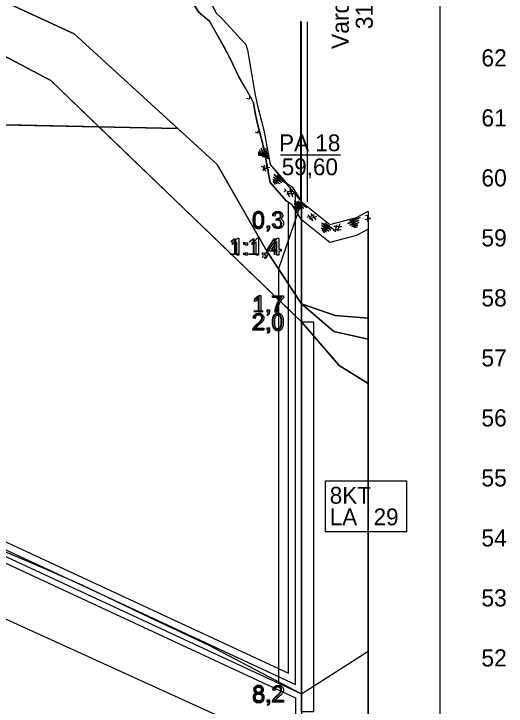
# Model space of a CAD drawing. Extents: x 532503 to 539665, y 6557663 to 6561526.
# Drawn here: x 537779.4 to 537943.4, y 6559649.9 to 6559880.7 of the extents above; entities that cross this region are included whole.
import ezdxf

# ---------------------------------------------------------------- set-up
doc = ezdxf.new("R2010")
doc.units = 0
for name, color, linetype in [('Default', 7, 'Continuous'), ('GEOLPUNKT', 7, 'Continuous'), ('illumineerimisjooned', 7, 'Continuous'), ('kataster', 7, 'Continuous'), ('maapind varasem', 7, 'Continuous'), ('mõõtpost parem', 7, 'Continuous'), ('PIIR', 7, 'Continuous'), ('Plokid', 7, 'Continuous'), ('Proovid', 7, 'Continuous'), ('RELJEEF', 7, 'Continuous'), ('Täide', 7, 'Continuous'), ('Veetase', 7, 'Continuous')]:
    doc.layers.add(name, color=color, linetype=linetype)

msp = doc.modelspace()

# ---------------------------------------------------------------- linework, layer by layer
at = {"layer": 'Default'}
for points in [[(537303.91, 6559920.78), (537332.99, 6559924), (537470.8, 6559937.4), (537470.8, 6559937.4), (537596.15, 6559901.6), (537596.15, 6559901.6), (537633.32, 6559922.6), (537745.67, 6559898.93), (537799.52, 6559873.96), (537847.17, 6559830.4), (537863.68, 6559801.53), (537875.25, 6559784), (537886.02, 6559774.84), (537897.46, 6559772.19)], [(537332.99, 6559924), (537470.8, 6559937.4), (537470.8, 6559937.4), (537596.15, 6559901.6), (537596.15, 6559901.6), (537633.32, 6559922.6), (537727.66, 6559892.38), (537791.69, 6559858.5), (537875.25, 6559778)], [(537303.91, 6559847.71), (537332.99, 6559848), (537470.8, 6559849.4), (537596.15, 6559847.6), (537833.98, 6559842.46)], [(537864.75, 6559830.4), (537870.28, 6559824.24), (537871.44, 6559823.5), (537872.15, 6559823), (537875.25, 6559818), (537884.66, 6559810.4), (537893.55, 6559812.84), (537897.46, 6559814.89)], [(537875.25, 6559778), (537887.82, 6559763.5), (537887.82, 6559763.5), (537897.46, 6559757.41)], [(537470.8, 6559750.72), (537596.15, 6559761.6), (537596.15, 6559761.6), (537637.63, 6559750.4), (537658, 6559744.14), (537701.62, 6559730.4), (537705.43, 6559729.02), (537718.89, 6559723.97), (537747.42, 6559713.34), (537755.24, 6559710.4), (537786.09, 6559697.32), (537802.07, 6559690.4), (537824.66, 6559679.52), (537844.13, 6559670.4), (537875.25, 6559654), (537897.46, 6559668.25)]]:
    msp.add_lwpolyline(points, dxfattribs=at)
at = {"layer": 'GEOLPUNKT'}
for p, q in [((537868.25, 6559833.68), (537888.25, 6559833.68)), ((537875.25, 6559818), (537875.25, 6559518))]:
    msp.add_line(p, q, dxfattribs=at)
at = {"layer": 'illumineerimisjooned'}
for p, q in [((537877.25, 6559818), (537877.25, 6559878)), ((537873.25, 6559657.14), (537873.25, 6559821.22))]:
    msp.add_line(p, q, dxfattribs=at)
msp.add_lwpolyline([(537335, 6559734.24), (537596.35, 6559763.64), (537748.15, 6559715.21), (537873.25, 6559657.14)], dxfattribs=at)
at = {"layer": 'kataster'}
msp.add_line((537875.04, 6559818.25), (537875.04, 6559878.25), dxfattribs=at)
at = {"layer": 'maapind varasem'}
msp.add_lwpolyline([(537776.56, 6559922.34), (537828.68, 6559905.51), (537836.34, 6559895.12), (537841.86, 6559890.4), (537846.88, 6559880.76), (537848.07, 6559879.75), (537848.76, 6559879.05), (537856.66, 6559870.4), (537857.06, 6559869.29), (537857.12, 6559869.07), (537857.16, 6559868.91), (537857.2, 6559868.69), (537857.69, 6559866), (537859.64, 6559854.28), (537860.46, 6559850.4), (537862.71, 6559841.91), (537864.75, 6559830.4), (537875.25, 6559818), (537884.66, 6559810.4), (537893.55, 6559812.84), (537897.46, 6559814.89)], dxfattribs=at)
at = {"layer": 'mõõtpost parem'}
msp.add_line((537921.46, 6559506), (537921.46, 6559986), dxfattribs=at)
at = {"layer": 'PIIR'}
for p, q in [((537875.25, 6559818), (537875.25, 6559878)), ((537875.25, 6559654), (537875.25, 6559818))]:
    msp.add_line(p, q, dxfattribs=at)
msp.add_lwpolyline([(537333, 6559732.01), (537596.15, 6559761.6), (537747.42, 6559713.34), (537875.25, 6559654)], dxfattribs=at)
at = {"layer": 'Plokid'}
for p, q in [((537870.85, 6559660.9), (537870.85, 6559817.88)), ((537873.25, 6559652.73), (537873.25, 6559518.45))]:
    msp.add_line(p, q, dxfattribs=at)
for points in [[(537337.4, 6559924.36), (537471.34, 6559937.39), (537471.34, 6559937.39), (537596.69, 6559901.59), (537596.69, 6559901.59), (537633.32, 6559922.6), (537727.66, 6559892.38), (537791.65, 6559858.53), (537791.67, 6559858.53), (537791.69, 6559858.5), (537870.85, 6559782.24)], [(537832.45, 6559889.51), (537838.46, 6559885.32), (537840.92, 6559881.3), (537844.55, 6559878.21), (537851.47, 6559865.77), (537854.28, 6559859.93), (537858.59, 6559852.33), (537859.19, 6559851), (537859.64, 6559848.28)], [(537859.64, 6559848.28), (537860.46, 6559844.4), (537862.71, 6559835.91), (537864.75, 6559824.4), (537870.28, 6559818.24), (537870.85, 6559817.88)], [(537337.4, 6559736.93), (537596.59, 6559766.08), (537749.02, 6559717.45), (537870.85, 6559660.9)], [(537337.4, 6559730.49), (537595.95, 6559759.57), (537746.69, 6559711.48), (537873.25, 6559652.73)]]:
    msp.add_lwpolyline(points, dxfattribs=at)
at = {"layer": 'Proovid'}
for points in [[(537866.34, 6559813.25), (537865.65, 6559813.38)], [(537866.94, 6559811.86), (537867.01, 6559812.46)], [(537865.58, 6559810.69), (537866.27, 6559810.78)], [(537863.92, 6559808.1), (537863.73, 6559808.39)], [(537863.78, 6559809.2), (537863.78, 6559809.99), (537864.56, 6559809.99), (537864.56, 6559809.2)], [(537864.16, 6559809.2), (537863.78, 6559809.2)], [(537859.58, 6559784.76), (537859.58, 6559785.42)], [(537861.64, 6559781.2), (537860.95, 6559781.2), (537860.95, 6559785.59)], [(537861.2, 6559786.83), (537861.64, 6559786.83), (537861.64, 6559781.2)], [(537865.62, 6559786.07), (537865.62, 6559786.73), (537869.25, 6559786.73), (537869.25, 6559786.2)], [(537868.36, 6559786.07), (537865.62, 6559786.07)], [(537863.92, 6559780.1), (537863.73, 6559780.39)], [(537863.78, 6559781.2), (537863.78, 6559781.99), (537864.56, 6559781.99), (537864.56, 6559781.2)], [(537864.16, 6559781.2), (537863.78, 6559781.2)], [(537867.11, 6559781.2), (537866.4, 6559781.2)], [(537859.82, 6559779.14), (537859.11, 6559779.21)], [(537862.69, 6559775.87), (537862.69, 6559775.2), (537858.99, 6559775.2)], [(537859.94, 6559775.87), (537862.69, 6559775.87)], [(537863.8, 6559775.2), (537863.8, 6559775.99), (537864.58, 6559775.99), (537864.58, 6559775.2)], [(537863.94, 6559774.1), (537863.75, 6559774.39)], [(537864.19, 6559775.2), (537863.8, 6559775.2)], [(537866.38, 6559655.14), (537865.67, 6559655.21)], [(537863.83, 6559651.2), (537863.83, 6559651.99), (537864.62, 6559651.99), (537864.62, 6559651.2)], [(537864.22, 6559651.2), (537863.83, 6559651.2)], [(537869.25, 6559651.87), (537869.25, 6559651.2), (537865.55, 6559651.2)], [(537866.5, 6559651.87), (537869.25, 6559651.87)], [(537863.98, 6559650.1), (537863.79, 6559650.39)]]:
    msp.add_lwpolyline(points, dxfattribs=at)
for points in [[(537875.25, 6559778), (537879.25, 6559778), (537879.25, 6559648), (537875.25, 6559648)], [(537883.25, 6559725), (537910.25, 6559725), (537910.25, 6559708), (537883.25, 6559708)]]:
    msp.add_lwpolyline(points, close=True, dxfattribs=at)
for points in [[(537859.05, 6559811.97), (537859.05, 6559812.96), (537859.26, 6559813.57), (537859.46, 6559814.17), (537859.87, 6559814.5), (537860.27, 6559814.83), (537860.88, 6559814.83), (537861.33, 6559814.83), (537861.67, 6559814.64), (537862.01, 6559814.46), (537862.23, 6559814.12), (537862.45, 6559813.78), (537862.58, 6559813.29), (537862.7, 6559812.8), (537862.7, 6559811.97), (537862.7, 6559810.98), (537862.5, 6559810.38), (537862.3, 6559809.77), (537861.9, 6559809.44), (537861.49, 6559809.11), (537860.88, 6559809.11), (537860.07, 6559809.11), (537859.61, 6559809.69), (537859.05, 6559810.39), (537859.05, 6559811.97)], [(537865.65, 6559813.38), (537865.78, 6559814.07), (537866.22, 6559814.45), (537866.67, 6559814.83), (537867.33, 6559814.83), (537867.79, 6559814.83), (537868.18, 6559814.63), (537868.56, 6559814.43), (537868.77, 6559814.09), (537868.97, 6559813.75), (537868.97, 6559813.37), (537868.97, 6559813.01), (537868.78, 6559812.71), (537868.58, 6559812.42), (537868.2, 6559812.24), (537868.7, 6559812.13), (537868.97, 6559811.77), (537869.25, 6559811.4), (537869.25, 6559810.86), (537869.25, 6559810.13), (537868.71, 6559809.62), (537868.18, 6559809.11), (537867.36, 6559809.11), (537866.62, 6559809.11), (537866.14, 6559809.55), (537865.65, 6559809.99), (537865.58, 6559810.69)], [(537859.76, 6559811.97), (537859.76, 6559810.59), (537860.08, 6559810.13), (537860.41, 6559809.67), (537860.88, 6559809.67), (537861.35, 6559809.67), (537861.67, 6559810.13), (537862, 6559810.59), (537862, 6559811.97), (537862, 6559813.35), (537861.67, 6559813.8), (537861.35, 6559814.26), (537860.87, 6559814.26), (537860.4, 6559814.26), (537860.12, 6559813.86), (537859.76, 6559813.35), (537859.76, 6559811.97)], [(537867.01, 6559812.46), (537867.08, 6559812.45), (537867.12, 6559812.45), (537867.56, 6559812.45), (537867.91, 6559812.68), (537868.27, 6559812.91), (537868.27, 6559813.39), (537868.27, 6559813.77), (537868.01, 6559814.01), (537867.75, 6559814.26), (537867.35, 6559814.26), (537866.95, 6559814.26), (537866.68, 6559814.01), (537866.41, 6559813.76), (537866.34, 6559813.25)], [(537866.27, 6559810.78), (537866.39, 6559810.19), (537866.67, 6559809.94), (537866.95, 6559809.68), (537867.36, 6559809.68), (537867.85, 6559809.68), (537868.18, 6559810.01), (537868.52, 6559810.35), (537868.52, 6559810.85), (537868.52, 6559811.32), (537868.21, 6559811.63), (537867.9, 6559811.94), (537867.42, 6559811.94), (537867.23, 6559811.94), (537866.94, 6559811.86)], [(537863.73, 6559808.39), (537863.95, 6559808.49), (537864.05, 6559808.67), (537864.15, 6559808.86), (537864.16, 6559809.2)], [(537864.56, 6559809.2), (537864.56, 6559808.77), (537864.4, 6559808.51), (537864.25, 6559808.24), (537863.92, 6559808.1)], [(537859.58, 6559785.42), (537860.16, 6559785.69), (537860.59, 6559786.08), (537861.02, 6559786.46), (537861.2, 6559786.83)], [(537860.95, 6559785.59), (537860.71, 6559785.35), (537860.3, 6559785.11), (537859.9, 6559784.87), (537859.58, 6559784.76)], [(537866.4, 6559781.2), (537866.42, 6559781.87), (537866.66, 6559782.8), (537866.91, 6559783.74), (537867.38, 6559784.61), (537867.84, 6559785.48), (537868.36, 6559786.07)], [(537869.25, 6559786.2), (537868.71, 6559785.63), (537868.19, 6559784.68), (537867.66, 6559783.74), (537867.38, 6559782.74), (537867.17, 6559782.04), (537867.11, 6559781.2)], [(537858.99, 6559775.2), (537858.98, 6559775.45), (537859.07, 6559775.68), (537859.21, 6559776.06), (537859.52, 6559776.43), (537859.83, 6559776.79), (537860.42, 6559777.27), (537861.33, 6559778.02), (537861.65, 6559778.46), (537861.97, 6559778.9), (537861.97, 6559779.29), (537861.97, 6559779.7), (537861.68, 6559779.98), (537861.39, 6559780.26), (537860.92, 6559780.26), (537860.42, 6559780.26), (537860.12, 6559779.96), (537859.83, 6559779.66), (537859.82, 6559779.14)], [(537859.11, 6559779.21), (537859.19, 6559780), (537859.66, 6559780.41), (537860.13, 6559780.83), (537860.93, 6559780.83), (537861.74, 6559780.83), (537862.21, 6559780.38), (537862.68, 6559779.93), (537862.68, 6559779.27), (537862.68, 6559778.94), (537862.54, 6559778.61), (537862.4, 6559778.29), (537862.08, 6559777.93), (537861.77, 6559777.57), (537861.03, 6559776.94), (537860.41, 6559776.42), (537860.23, 6559776.24), (537860.06, 6559776.05), (537859.94, 6559775.87)], [(537863.73, 6559780.39), (537863.95, 6559780.49), (537864.05, 6559780.67), (537864.15, 6559780.86), (537864.16, 6559781.2)], [(537864.56, 6559781.2), (537864.56, 6559780.77), (537864.4, 6559780.51), (537864.25, 6559780.24), (537863.92, 6559780.1)], [(537865.6, 6559777.97), (537865.6, 6559778.96), (537865.8, 6559779.57), (537866.01, 6559780.17), (537866.41, 6559780.5), (537866.81, 6559780.83), (537867.42, 6559780.83), (537867.87, 6559780.83), (537868.21, 6559780.64), (537868.55, 6559780.46), (537868.77, 6559780.12), (537869, 6559779.78), (537869.12, 6559779.29), (537869.25, 6559778.8), (537869.25, 6559777.97), (537869.25, 6559776.98), (537869.04, 6559776.38), (537868.84, 6559775.77), (537868.44, 6559775.44), (537868.04, 6559775.11), (537867.42, 6559775.11), (537866.61, 6559775.11), (537866.15, 6559775.69), (537865.6, 6559776.39), (537865.6, 6559777.97)], [(537866.31, 6559777.97), (537866.31, 6559776.59), (537866.63, 6559776.13), (537866.95, 6559775.67), (537867.42, 6559775.67), (537867.89, 6559775.67), (537868.22, 6559776.13), (537868.54, 6559776.59), (537868.54, 6559777.97), (537868.54, 6559779.35), (537868.22, 6559779.8), (537867.9, 6559780.26), (537867.41, 6559780.26), (537866.94, 6559780.26), (537866.66, 6559779.86), (537866.31, 6559779.35), (537866.31, 6559777.97)], [(537863.75, 6559774.39), (537863.97, 6559774.49), (537864.07, 6559774.67), (537864.17, 6559774.86), (537864.19, 6559775.2)], [(537864.58, 6559775.2), (537864.58, 6559774.77), (537864.43, 6559774.51), (537864.27, 6559774.24), (537863.94, 6559774.1)], [(537860.18, 6559654.24), (537859.75, 6559654.4), (537859.54, 6559654.69), (537859.33, 6559654.98), (537859.33, 6559655.38), (537859.33, 6559655.99), (537859.77, 6559656.41), (537860.21, 6559656.83), (537860.94, 6559656.83), (537861.67, 6559656.83), (537862.12, 6559656.4), (537862.56, 6559655.98), (537862.56, 6559655.37), (537862.56, 6559654.98), (537862.36, 6559654.69), (537862.15, 6559654.4), (537861.74, 6559654.24), (537862.25, 6559654.08), (537862.52, 6559653.7), (537862.79, 6559653.33), (537862.79, 6559652.81), (537862.79, 6559652.09), (537862.29, 6559651.6), (537861.78, 6559651.11), (537860.95, 6559651.11), (537860.12, 6559651.11), (537859.61, 6559651.6), (537859.11, 6559652.09), (537859.11, 6559652.83), (537859.11, 6559653.37), (537859.38, 6559653.74), (537859.66, 6559654.11), (537860.18, 6559654.24)], [(537860.04, 6559655.41), (537860.04, 6559655.01), (537860.29, 6559654.76), (537860.55, 6559654.51), (537860.95, 6559654.51), (537861.35, 6559654.51), (537861.6, 6559654.76), (537861.85, 6559655.01), (537861.85, 6559655.37), (537861.85, 6559655.75), (537861.6, 6559656.01), (537861.34, 6559656.26), (537860.95, 6559656.26), (537860.55, 6559656.26), (537860.3, 6559656.01), (537860.04, 6559655.76), (537860.04, 6559655.41)], [(537865.55, 6559651.2), (537865.54, 6559651.45), (537865.63, 6559651.68), (537865.77, 6559652.06), (537866.08, 6559652.43), (537866.39, 6559652.79), (537866.98, 6559653.27), (537867.89, 6559654.02), (537868.21, 6559654.46), (537868.53, 6559654.9), (537868.53, 6559655.29), (537868.53, 6559655.7), (537868.24, 6559655.98), (537867.95, 6559656.26), (537867.48, 6559656.26), (537866.98, 6559656.26), (537866.68, 6559655.96), (537866.39, 6559655.66), (537866.38, 6559655.14)], [(537865.67, 6559655.21), (537865.75, 6559656), (537866.22, 6559656.41), (537866.69, 6559656.83), (537867.49, 6559656.83), (537868.3, 6559656.83), (537868.77, 6559656.38), (537869.24, 6559655.93), (537869.24, 6559655.27), (537869.24, 6559654.94), (537869.1, 6559654.61), (537868.96, 6559654.29), (537868.65, 6559653.93), (537868.33, 6559653.57), (537867.59, 6559652.94), (537866.97, 6559652.42), (537866.79, 6559652.24), (537866.62, 6559652.05), (537866.5, 6559651.87)], [(537859.81, 6559652.82), (537859.81, 6559652.53), (537859.95, 6559652.25), (537860.09, 6559651.98), (537860.36, 6559651.83), (537860.64, 6559651.67), (537860.96, 6559651.67), (537861.45, 6559651.67), (537861.77, 6559651.99), (537862.08, 6559652.31), (537862.08, 6559652.8), (537862.08, 6559653.3), (537861.76, 6559653.62), (537861.43, 6559653.95), (537860.93, 6559653.95), (537860.45, 6559653.95), (537860.13, 6559653.62), (537859.81, 6559653.3), (537859.81, 6559652.82)], [(537863.79, 6559650.39), (537864.01, 6559650.49), (537864.11, 6559650.67), (537864.21, 6559650.86), (537864.22, 6559651.2)], [(537864.62, 6559651.2), (537864.62, 6559650.77), (537864.46, 6559650.51), (537864.31, 6559650.24), (537863.98, 6559650.1)]]:
    msp.add_open_spline(points, degree=3, dxfattribs=at)
at = {"layer": 'RELJEEF'}
for p, q in [((537875.25, 6559818), (537867.54, 6559795.68)), ((537867.54, 6559795.68), (537867.54, 6559657.58))]:
    msp.add_line(p, q, dxfattribs=at)
for points in [[(537853.9, 6559805.9), (537854.34, 6559805.9), (537854.34, 6559800.28)], [(537860.42, 6559805.9), (537860.87, 6559805.9), (537860.87, 6559800.28)], [(537867, 6559800.28), (537867, 6559801.62), (537864.58, 6559801.62), (537864.58, 6559802.25), (537867.13, 6559805.88), (537867.69, 6559805.88), (537867.69, 6559802.25), (537868.45, 6559802.25), (537868.45, 6559801.62), (537867.69, 6559801.62), (537867.69, 6559800.28), (537867, 6559800.28)], [(537852.28, 6559803.83), (537852.28, 6559804.5)], [(537854.34, 6559800.28), (537853.66, 6559800.28), (537853.66, 6559804.66)], [(537856.49, 6559803.56), (537856.49, 6559804.34), (537857.27, 6559804.34), (537857.27, 6559803.56), (537856.49, 6559803.56)], [(537858.8, 6559803.83), (537858.8, 6559804.5)], [(537860.87, 6559800.28), (537860.18, 6559800.28), (537860.18, 6559804.66)], [(537867, 6559802.25), (537867, 6559804.78), (537865.25, 6559802.25), (537867, 6559802.25)], [(537856.49, 6559800.28), (537856.49, 6559801.06), (537857.27, 6559801.06), (537857.27, 6559800.28), (537856.49, 6559800.28)], [(537863, 6559800.28), (537863, 6559801.06), (537863.78, 6559801.06), (537863.78, 6559800.28)], [(537863.15, 6559799.17), (537862.95, 6559799.47)], [(537863.39, 6559800.28), (537863, 6559800.28)]]:
    msp.add_lwpolyline(points, dxfattribs=at)
for points in [[(537852.28, 6559804.5), (537852.86, 6559804.77), (537853.29, 6559805.15), (537853.72, 6559805.54), (537853.9, 6559805.9)], [(537858.8, 6559804.5), (537859.38, 6559804.77), (537859.81, 6559805.15), (537860.24, 6559805.54), (537860.42, 6559805.9)], [(537853.66, 6559804.66), (537853.41, 6559804.42), (537853.01, 6559804.19), (537852.6, 6559803.95), (537852.28, 6559803.83)], [(537860.18, 6559804.66), (537859.93, 6559804.42), (537859.53, 6559804.19), (537859.13, 6559803.95), (537858.8, 6559803.83)], [(537862.95, 6559799.47), (537863.17, 6559799.56), (537863.27, 6559799.75), (537863.38, 6559799.93), (537863.39, 6559800.28)], [(537863.78, 6559800.28), (537863.78, 6559799.85), (537863.63, 6559799.58), (537863.48, 6559799.32), (537863.15, 6559799.17)]]:
    msp.add_open_spline(points, degree=3, dxfattribs=at)
at = {"layer": 'Täide'}
for p, q in [((537745.67, 6559898.93), (537799.52, 6559873.96)), ((537833.98, 6559842.46), (537799.52, 6559873.96)), ((537799.52, 6559873.96), (537833.98, 6559842.46)), ((537791.69, 6559858.5), (537807.75, 6559843.03)), ((537859.19, 6559851), (537858.59, 6559852.33)), ((537807.75, 6559843.03), (537833.47, 6559818.25)), ((537833.98, 6559842.46), (537807.75, 6559843.03)), ((537833.98, 6559842.46), (537807.75, 6559843.03)), ((537807.75, 6559843.03), (537833.47, 6559818.25)), ((537807.75, 6559843.03), (537833.98, 6559842.46)), ((537847.17, 6559830.4), (537833.98, 6559842.46)), ((537847.17, 6559830.4), (537833.98, 6559842.46)), ((537833.98, 6559842.46), (537847.17, 6559830.4)), ((537847.17, 6559830.4), (537863.68, 6559801.53)), ((537833.47, 6559818.25), (537833.47, 6559818.25)), ((537833.47, 6559818.25), (537833.47, 6559818.25)), ((537833.47, 6559818.25), (537875.25, 6559778)), ((537897.46, 6559779.26), (537897.46, 6559808.89)), ((537863.68, 6559801.53), (537875.25, 6559784)), ((537886.02, 6559774.84), (537875.25, 6559784)), ((537886.45, 6559780.15), (537875.25, 6559784)), ((537875.25, 6559784), (537886.45, 6559780.15)), ((537897.46, 6559779.26), (537886.45, 6559780.15)), ((537886.45, 6559780.15), (537897.46, 6559779.26)), ((537875.25, 6559778), (537887.82, 6559763.5)), ((537897.46, 6559757.41), (537897.46, 6559779.26)), ((537897.46, 6559772.19), (537886.02, 6559774.84)), ((537897.46, 6559757.41), (537897.46, 6559772.19)), ((537887.82, 6559763.5), (537897.46, 6559757.41))]:
    msp.add_line(p, q, dxfattribs=at)
for points in [[(537897.46, 6559757.41), (537887.82, 6559763.5), (537875.25, 6559778), (537791.69, 6559858.5), (537727.66, 6559892.38), (537633.32, 6559922.6), (537596.15, 6559901.6), (537470.8, 6559937.4), (537332.99, 6559924), (537303.91, 6559920.78)], [(537799.52, 6559873.96), (537745.67, 6559898.93), (537633.32, 6559922.6)], [(537633.32, 6559922.6), (537727.66, 6559892.38), (537791.69, 6559858.5)], [(537775.61, 6559843.72), (537833.98, 6559842.46), (537799.52, 6559873.96), (537745.67, 6559898.93)], [(537858.59, 6559852.33), (537856.61, 6559855.9), (537854.28, 6559859.93), (537851.47, 6559865.77), (537849.43, 6559869.71), (537844.55, 6559878.21), (537841.95, 6559880.3), (537841.36, 6559880.95), (537840.92, 6559881.3), (537838.46, 6559885.32), (537832.45, 6559889.51)], [(537857.86, 6559853), (537857.85, 6559852.21), (537857.06, 6559852.48)], [(537807.75, 6559843.03), (537596.15, 6559847.6), (537470.8, 6559849.4)], [(537897.46, 6559808.89), (537893.55, 6559806.84), (537884.66, 6559804.4), (537875.25, 6559812), (537872.15, 6559817), (537871.44, 6559817.5), (537870.28, 6559818.24), (537864.75, 6559824.4), (537862.71, 6559835.91), (537860.46, 6559844.4), (537859.64, 6559848.28), (537859.19, 6559851)], [(537897.46, 6559757.41), (537887.82, 6559763.5), (537875.25, 6559778), (537833.47, 6559818.25), (537807.75, 6559843.03)], [(537860.72, 6559841.69), (537860.68, 6559840.9), (537859.9, 6559841.2)], [(537863.23, 6559835.91), (537864.07, 6559832.29), (537862.4, 6559836.55), (537863.16, 6559832.8), (537861.84, 6559835.92), (537862.43, 6559832.85), (537861.25, 6559835.34), (537861.68, 6559833.32), (537860.92, 6559834.68), (537860.95, 6559833.49)], [(537875.25, 6559784), (537863.68, 6559801.53), (537847.17, 6559830.4)], [(537875.25, 6559784), (537863.68, 6559801.53), (537847.17, 6559830.4)], [(537862.74, 6559830.23), (537862.7, 6559829.45), (537861.92, 6559829.74)], [(537862.22, 6559828.62), (537862.52, 6559828.67), (537862.66, 6559828.62), (537862.7, 6559829.45), (537863.77, 6559829.02), (537863.84, 6559829.86)], [(537864.68, 6559829.47), (537863.81, 6559829.32), (537862.7, 6559829.15), (537863.21, 6559828.24)], [(537863.97, 6559830.18), (537863.43, 6559830.08), (537863.81, 6559829.32), (537864.27, 6559828.44)], [(537867.1, 6559826.99), (537869.73, 6559824.35), (537866.05, 6559827.09), (537868.68, 6559824.31), (537865.91, 6559826.26), (537868.03, 6559823.97), (537865.72, 6559825.45), (537867.14, 6559823.97), (537865.78, 6559824.72), (537866.44, 6559823.73)], [(537869.59, 6559822.3), (537870.15, 6559821.74), (537869.4, 6559821.36)], [(537870.39, 6559820.53), (537870.64, 6559820.69), (537870.8, 6559820.69), (537870.53, 6559821.48), (537871.68, 6559821.48), (537871.43, 6559822.28)], [(537872.8, 6559820.66), (537871.92, 6559820.67), (537870.8, 6559820.69), (537871.14, 6559819.71)], [(537872.22, 6559821.49), (537871.68, 6559821.48), (537871.92, 6559820.67), (537872.22, 6559819.72)], [(537833.47, 6559818.25), (537833.47, 6559818.25), (537833.47, 6559818.25)], [(537833.47, 6559818.25), (537875.25, 6559778), (537887.82, 6559763.5), (537897.46, 6559757.41)], [(537874, 6559818.32), (537877.02, 6559816.14), (537872.95, 6559818.26), (537875.99, 6559815.93), (537872.94, 6559817.42), (537875.41, 6559815.5), (537872.88, 6559816.59), (537874.53, 6559815.35), (537873.06, 6559815.88), (537873.87, 6559815)], [(537897.46, 6559814.89), (537897.46, 6559636), (537897.46, 6559518)], [(537877.36, 6559813.72), (537877.85, 6559813.1), (537877.06, 6559812.81)], [(537878.03, 6559812.16), (537878.22, 6559812.4), (537878.36, 6559812.45), (537877.85, 6559813.1), (537878.94, 6559813.49), (537878.44, 6559814.16)], [(537880.27, 6559813.08), (537879.44, 6559812.8), (537878.36, 6559812.45), (537879.01, 6559811.64)], [(537879.45, 6559813.68), (537878.94, 6559813.49), (537879.44, 6559812.8), (537880.03, 6559812)], [(537891.27, 6559811.67), (537894.8, 6559812.84), (537890.71, 6559810.78), (537894.37, 6559811.89), (537891.39, 6559810.28), (537894.39, 6559811.16), (537892.03, 6559809.74), (537893.99, 6559810.36), (537892.71, 6559809.48), (537893.89, 6559809.62)], [(537898.22, 6559812.13), (537898.08, 6559812.4), (537898.09, 6559812.55), (537897.29, 6559812.34), (537897.37, 6559813.49), (537896.55, 6559813.3)], [(537883.05, 6559811.02), (537886.06, 6559808.84), (537882, 6559810.95), (537885.04, 6559808.63), (537881.99, 6559810.11), (537884.45, 6559808.19), (537881.93, 6559809.28), (537883.58, 6559808.05), (537882.11, 6559808.57), (537882.92, 6559807.7)], [(537887.01, 6559810.3), (537886.86, 6559809.77), (537887.72, 6559809.77), (537888.71, 6559809.79)], [(537887.97, 6559810.62), (537887.72, 6559809.77), (537887.37, 6559808.7), (537888.41, 6559808.75)], [(537896.53, 6559812.14), (537897.29, 6559812.34), (537897.24, 6559811.5)], [(537885.76, 6559808.63), (537886.54, 6559808.66), (537886.32, 6559807.86)], [(537887.41, 6559808.26), (537887.33, 6559808.55), (537887.37, 6559808.7), (537886.54, 6559808.66), (537886.86, 6559809.77), (537886.03, 6559809.76)], [(537897.46, 6559518), (537897.46, 6559636), (537897.46, 6559757.41)], [(537897.46, 6559518), (537897.46, 6559636), (537897.46, 6559757.41)]]:
    msp.add_lwpolyline(points, dxfattribs=at)
at = {"layer": 'Veetase'}
msp.add_lwpolyline([(537897.46, 6559630.11), (537875.25, 6559634), (537737.03, 6559696.96), (537596.15, 6559741.6), (537333, 6559712), (537303.91, 6559709.89)], dxfattribs=at)

# ---------------------------------------------------------------- texts
at = {"layer": 'GEOLPUNKT'}
for s, p in [('PA 18', (537867.77, 6559834.88)), ('59,60', (537868.65, 6559826.88))]:
    msp.add_text(s, height=5.6, dxfattribs=at).set_placement(p)
at = {"layer": 'kataster'}
for s, p in [('Vardi metskond 244', (537891, 6559868.94)), ('31701:001:1353', (537899, 6559875.56))]:
    msp.add_text(s, height=5.7, rotation=90, dxfattribs=at).set_placement(p)
at = {"layer": 'mõõtpost parem'}
for s, p in [('62', (537935.16, 6559863.15)), ('61', (537935.16, 6559843.15)), ('60', (537935.16, 6559823.15)), ('59', (537935.16, 6559803.15)), ('58', (537935.16, 6559783.15)), ('57', (537935.16, 6559763.15)), ('56', (537935.16, 6559743.15)), ('55', (537935.16, 6559723.15)), ('54', (537935.16, 6559703.15)), ('53', (537935.16, 6559683.15)), ('52', (537935.16, 6559663.15))]:
    msp.add_text(s, height=5.7, dxfattribs=at).set_placement(p)
at = {"layer": 'Proovid'}
for s, p in [('0,3', (537858.73, 6559809.2)), ('1,7', (537858.73, 6559781.2)), ('2,0', (537858.75, 6559775.2)), ('8KT', (537884.65, 6559717.4)), ('LA', (537884.65, 6559710.2)), ('29', (537899.25, 6559710.2)), ('8,2', (537858.79, 6559651.2))]:
    msp.add_text(s, height=5.6, dxfattribs=at).set_placement(p)
at = {"layer": 'RELJEEF'}
msp.add_text('1:1,4', height=5.6, dxfattribs=at).set_placement((537850.86, 6559800.28))

doc.saveas('drawing.dxf')
